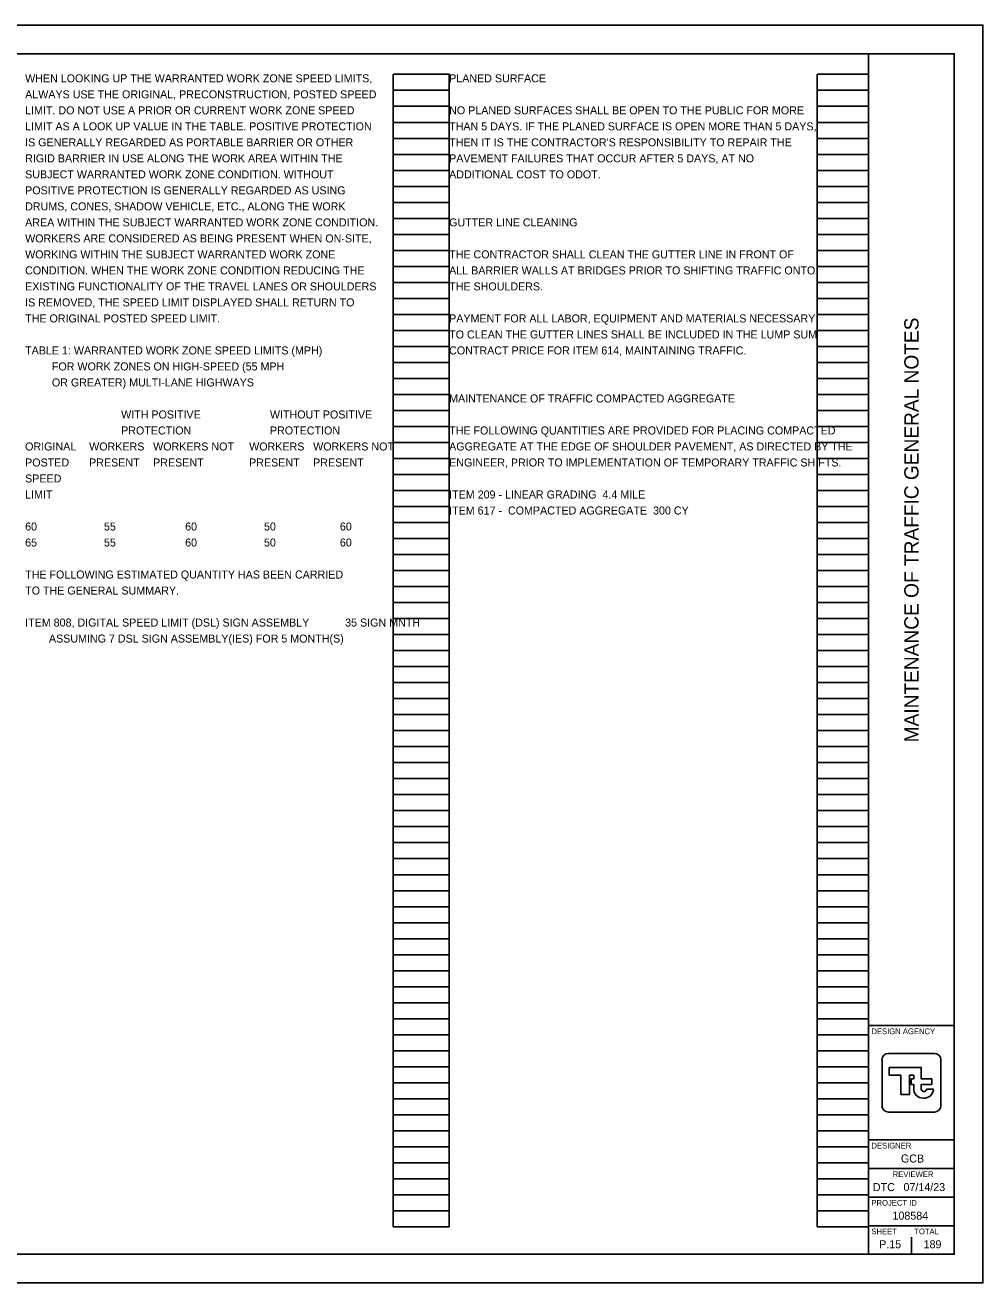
# Model space of a CAD drawing. Extents: x 0 to 34, y -3.9 to 22.
# Drawn here: x 17.24 to 34, y 0 to 22 of the extents above; entities that cross this region are included whole.
import ezdxf

# ---------------------------------------------------------------- set-up
doc = ezdxf.new("R2010")
doc.units = 0
for name, color, linetype in [('SH_Border', 7, 'Continuous'), ('SH_Cut_Line', 7, 'Continuous'), ('SH_Data', 7, 'Continuous'), ('SH_Text', 7, 'Continuous')]:
    doc.layers.add(name, color=color, linetype=linetype)

msp = doc.modelspace()

# ---------------------------------------------------------------- linework, layer by layer
at = {"layer": 'SH_Border'}
for p, q in [((32, 0.5), (32, 21.5)), ((32, 4.5), (33.5, 4.5)), ((32, 2.5), (33.5, 2.5)), ((32, 2), (33.5, 2)), ((32, 1.5), (33.5, 1.5)), ((32, 1), (33.5, 1))]:
    msp.add_line(p, q, dxfattribs=at)
msp.add_lwpolyline([(1.5, 21.5), (33.5, 21.5), (33.5, 0.5), (1.5, 0.5)], close=True, dxfattribs=at)
at = {"layer": 'SH_Cut_Line'}
msp.add_lwpolyline([(0, 0), (34, 0), (34, 22), (0, 22)], close=True, dxfattribs=at)
at = {"layer": 'SH_Data'}
for p, q in [((23.68, 0.98), (23.68, 21.14)), ((23.68, 21.14), (24.66, 21.14)), ((24.66, 0.98), (24.66, 21.14)), ((31.1, 0.98), (31.1, 21.14)), ((31.1, 21.14), (32, 21.14)), ((32, 0.98), (32, 21.14)), ((23.68, 20.86), (24.66, 20.86)), ((31.1, 20.86), (32, 20.86)), ((23.68, 20.58), (24.66, 20.58)), ((31.1, 20.58), (32, 20.58)), ((23.68, 20.3), (24.66, 20.3)), ((31.1, 20.3), (32, 20.3)), ((23.68, 20.02), (24.66, 20.02)), ((31.1, 20.02), (32, 20.02)), ((23.68, 19.74), (24.66, 19.74)), ((31.1, 19.74), (32, 19.74)), ((23.68, 19.46), (24.66, 19.46)), ((31.1, 19.46), (32, 19.46)), ((23.68, 19.18), (24.66, 19.18)), ((31.1, 19.18), (32, 19.18)), ((23.68, 18.9), (24.66, 18.9)), ((31.1, 18.9), (32, 18.9)), ((23.68, 18.62), (24.66, 18.62)), ((31.1, 18.62), (32, 18.62)), ((23.68, 18.34), (24.66, 18.34)), ((31.1, 18.34), (32, 18.34)), ((23.68, 18.06), (24.66, 18.06)), ((31.1, 18.06), (32, 18.06)), ((23.68, 17.78), (24.66, 17.78)), ((31.1, 17.78), (32, 17.78)), ((23.68, 17.5), (24.66, 17.5)), ((31.1, 17.5), (32, 17.5)), ((23.68, 17.22), (24.66, 17.22)), ((31.1, 17.22), (32, 17.22)), ((23.68, 16.94), (24.66, 16.94)), ((31.1, 16.94), (32, 16.94)), ((23.68, 16.66), (24.66, 16.66)), ((31.1, 16.66), (32, 16.66)), ((23.68, 16.38), (24.66, 16.38)), ((31.1, 16.38), (32, 16.38)), ((23.68, 16.1), (24.66, 16.1)), ((31.1, 16.1), (32, 16.1)), ((23.68, 15.82), (24.66, 15.82)), ((31.1, 15.82), (32, 15.82)), ((23.68, 15.54), (24.66, 15.54)), ((31.1, 15.54), (32, 15.54)), ((23.68, 15.26), (24.66, 15.26)), ((31.1, 15.26), (32, 15.26)), ((23.68, 14.98), (24.66, 14.98)), ((31.1, 14.98), (32, 14.98)), ((23.68, 14.7), (24.66, 14.7)), ((31.1, 14.7), (32, 14.7)), ((23.68, 14.42), (24.66, 14.42)), ((31.1, 14.42), (32, 14.42)), ((23.68, 14.14), (24.66, 14.14)), ((31.1, 14.14), (32, 14.14)), ((23.68, 13.86), (24.66, 13.86)), ((31.1, 13.86), (32, 13.86)), ((23.68, 13.58), (24.66, 13.58)), ((31.1, 13.58), (32, 13.58)), ((23.68, 13.3), (24.66, 13.3)), ((31.1, 13.3), (32, 13.3)), ((23.68, 13.02), (24.66, 13.02)), ((31.1, 13.02), (32, 13.02)), ((23.68, 12.74), (24.66, 12.74)), ((31.1, 12.74), (32, 12.74)), ((23.68, 12.46), (24.66, 12.46)), ((31.1, 12.46), (32, 12.46)), ((23.68, 12.18), (24.66, 12.18)), ((31.1, 12.18), (32, 12.18)), ((23.68, 11.9), (24.66, 11.9)), ((31.1, 11.9), (32, 11.9)), ((23.68, 11.62), (24.66, 11.62)), ((31.1, 11.62), (32, 11.62)), ((23.68, 11.34), (24.66, 11.34)), ((31.1, 11.34), (32, 11.34)), ((23.68, 11.06), (24.66, 11.06)), ((31.1, 11.06), (32, 11.06)), ((23.68, 10.78), (24.66, 10.78)), ((31.1, 10.78), (32, 10.78)), ((23.68, 10.5), (24.66, 10.5)), ((31.1, 10.5), (32, 10.5)), ((23.68, 10.22), (24.66, 10.22)), ((31.1, 10.22), (32, 10.22)), ((23.68, 9.94), (24.66, 9.94)), ((31.1, 9.94), (32, 9.94)), ((23.68, 9.66), (24.66, 9.66)), ((31.1, 9.66), (32, 9.66)), ((23.68, 9.38), (24.66, 9.38)), ((31.1, 9.38), (32, 9.38)), ((23.68, 9.1), (24.66, 9.1)), ((31.1, 9.1), (32, 9.1)), ((23.68, 8.82), (24.66, 8.82)), ((31.1, 8.82), (32, 8.82)), ((23.68, 8.54), (24.66, 8.54)), ((31.1, 8.54), (32, 8.54)), ((23.68, 8.26), (24.66, 8.26)), ((31.1, 8.26), (32, 8.26)), ((23.68, 7.98), (24.66, 7.98)), ((31.1, 7.98), (32, 7.98)), ((23.68, 7.7), (24.66, 7.7)), ((31.1, 7.7), (32, 7.7)), ((23.68, 7.42), (24.66, 7.42)), ((31.1, 7.42), (32, 7.42)), ((23.68, 7.14), (24.66, 7.14)), ((31.1, 7.14), (32, 7.14)), ((23.68, 6.86), (24.66, 6.86)), ((31.1, 6.86), (32, 6.86)), ((23.68, 6.58), (24.66, 6.58)), ((31.1, 6.58), (32, 6.58)), ((23.68, 6.3), (24.66, 6.3)), ((31.1, 6.3), (32, 6.3)), ((23.68, 6.02), (24.66, 6.02)), ((31.1, 6.02), (32, 6.02)), ((23.68, 5.74), (24.66, 5.74)), ((31.1, 5.74), (32, 5.74)), ((23.68, 5.46), (24.66, 5.46)), ((31.1, 5.46), (32, 5.46)), ((23.68, 5.18), (24.66, 5.18)), ((31.1, 5.18), (32, 5.18)), ((23.68, 4.9), (24.66, 4.9)), ((31.1, 4.9), (32, 4.9)), ((23.68, 4.62), (24.66, 4.62)), ((31.1, 4.62), (32, 4.62)), ((23.68, 4.34), (24.66, 4.34)), ((31.1, 4.34), (32, 4.34)), ((23.68, 4.06), (24.66, 4.06)), ((31.1, 4.06), (32, 4.06)), ((23.68, 3.78), (24.66, 3.78)), ((31.1, 3.78), (32, 3.78)), ((23.68, 3.5), (24.66, 3.5)), ((31.1, 3.5), (32, 3.5)), ((32.75, 3.5), (32.75, 3.5)), ((32.791, 3.415), (32.791, 3.415)), ((33.136, 3.385), (33.015, 3.385)), ((23.68, 3.22), (24.66, 3.22)), ((31.1, 3.22), (32, 3.22)), ((23.68, 2.94), (24.66, 2.94)), ((31.1, 2.94), (32, 2.94)), ((23.68, 2.66), (24.66, 2.66)), ((31.1, 2.66), (32, 2.66)), ((23.68, 2.38), (24.66, 2.38)), ((31.1, 2.38), (32, 2.38)), ((23.68, 2.1), (24.66, 2.1)), ((31.1, 2.1), (32, 2.1)), ((23.68, 1.82), (24.66, 1.82)), ((31.1, 1.82), (32, 1.82)), ((23.68, 1.54), (24.66, 1.54)), ((31.1, 1.54), (32, 1.54)), ((23.68, 1.26), (24.66, 1.26)), ((31.1, 1.26), (32, 1.26)), ((23.68, 0.98), (24.66, 0.98)), ((31.1, 0.98), (32, 0.98)), ((32.375, 0.675), (32.375, 0.675)), ((32.75, 0.5), (32.75, 0.8))]:
    msp.add_line(p, q, dxfattribs=at)
for points in [[(32.348, 4.014), (33.152, 4.014)], [(32.236, 3.099), (32.236, 3.901)], [(32.922, 3.399), (32.922, 3.47), (33.107, 3.47), (33.107, 3.568), (32.922, 3.568), (32.922, 3.768), (32.361, 3.768), (32.361, 3.632), (32.566, 3.632), (32.566, 3.294), (32.715, 3.294), (32.715, 3.63), (32.79, 3.63), (32.79, 3.568), (32.748, 3.568), (32.748, 3.47), (32.79, 3.47), (32.79, 3.415), (32.791, 3.415)], [(33.264, 3.901), (33.264, 3.099)], [(33.152, 2.986), (32.348, 2.986)]]:
    msp.add_lwpolyline(points, dxfattribs=at)
for centre, radius, start, end in [((32.348, 3.901), 0.113, 90, 180), ((33.152, 3.901), 0.113, 360, 90), ((32.949, 3.392), 0.16, 171.8856, 274.8323), ((32.968, 3.392), 0.0473, 171.8856, 350.9243), ((32.976, 3.392), 0.16, 265.1677, 357.3201), ((32.348, 3.099), 0.113, 180, 270), ((33.152, 3.099), 0.113, 270, 360)]:
    msp.add_arc(centre, radius, start, end, dxfattribs=at)

# ---------------------------------------------------------------- texts
msp.add_text('MAINTENANCE OF TRAFFIC GENERAL NOTES', height=0.25, rotation=90, dxfattribs=at).set_placement((32.875, 9.455))
for s, height, p in [('DESIGN AGENCY', 0.1, (32.05, 4.35)), ('DESIGNER', 0.1, (32.05, 2.35)), ('GCB', 0.14, (32.566, 2.105)), ('REVIEWER', 0.1, (32.422, 1.85)), ('DTC', 0.14, (32.076, 1.605)), ('07/14/23', 0.14, (32.611, 1.605)), ('PROJECT ID', 0.1, (32.05, 1.35)), ('108584', 0.14, (32.418, 1.105)), ('SHEET', 0.1, (32.05, 0.85)), ('TOTAL', 0.1, (32.8, 0.85)), ('P.15', 0.14, (32.185, 0.605)), ('189', 0.14, (32.963, 0.605))]:
    msp.add_text(s, height=height, dxfattribs=at).set_placement(p)
at = {"layer": 'SH_Text'}
for s, p in [('WHEN LOOKING UP THE WARRANTED WORK ZONE SPEED LIMITS,', (17.24, 21)), ('PLANED SURFACE', (24.66, 21)), ('ALWAYS USE THE ORIGINAL, PRECONSTRUCTION, POSTED SPEED', (17.24, 20.72)), ('LIMIT. DO NOT USE A PRIOR OR CURRENT WORK ZONE SPEED', (17.24, 20.44)), ('NO PLANED SURFACES SHALL BE OPEN TO THE PUBLIC FOR MORE', (24.66, 20.44)), ('LIMIT AS A LOOK UP VALUE IN THE TABLE. POSITIVE PROTECTION', (17.24, 20.16)), ('THAN 5 DAYS. IF THE PLANED SURFACE IS OPEN MORE THAN 5 DAYS,', (24.66, 20.16)), ('IS GENERALLY REGARDED AS PORTABLE BARRIER OR OTHER', (17.24, 19.88)), ("THEN IT IS THE CONTRACTOR'S RESPONSIBILITY TO REPAIR THE", (24.66, 19.88)), ('RIGID BARRIER IN USE ALONG THE WORK AREA WITHIN THE', (17.24, 19.6)), ('PAVEMENT FAILURES THAT OCCUR AFTER 5 DAYS, AT NO', (24.66, 19.6)), ('SUBJECT WARRANTED WORK ZONE CONDITION. WITHOUT', (17.24, 19.32)), ('ADDITIONAL COST TO ODOT.', (24.66, 19.32)), ('POSITIVE PROTECTION IS GENERALLY REGARDED AS USING', (17.24, 19.04)), ('DRUMS, CONES, SHADOW VEHICLE, ETC., ALONG THE WORK', (17.24, 18.76)), ('AREA WITHIN THE SUBJECT WARRANTED WORK ZONE CONDITION.', (17.24, 18.48)), ('GUTTER LINE CLEANING', (24.66, 18.48)), ('WORKERS ARE CONSIDERED AS BEING PRESENT WHEN ON-SITE,', (17.24, 18.2)), ('WORKING WITHIN THE SUBJECT WARRANTED WORK ZONE', (17.24, 17.92)), ('THE CONTRACTOR SHALL CLEAN THE GUTTER LINE IN FRONT OF', (24.66, 17.92)), ('CONDITION. WHEN THE WORK ZONE CONDITION REDUCING THE', (17.24, 17.64)), ('ALL BARRIER WALLS AT BRIDGES PRIOR TO SHIFTING TRAFFIC ONTO', (24.66, 17.64)), ('EXISTING FUNCTIONALITY OF THE TRAVEL LANES OR SHOULDERS', (17.24, 17.36)), ('THE SHOULDERS.', (24.66, 17.36)), ('IS REMOVED, THE SPEED LIMIT DISPLAYED SHALL RETURN TO', (17.24, 17.08)), ('THE ORIGINAL POSTED SPEED LIMIT.', (17.24, 16.8)), ('PAYMENT FOR ALL LABOR, EQUIPMENT AND MATERIALS NECESSARY', (24.66, 16.8)), ('TO CLEAN THE GUTTER LINES SHALL BE INCLUDED IN THE LUMP SUM', (24.66, 16.52)), ('TABLE 1: WARRANTED WORK ZONE SPEED LIMITS (MPH)', (17.24, 16.24)), ('CONTRACT PRICE FOR ITEM 614, MAINTAINING TRAFFIC.', (24.66, 16.24)), ('         FOR WORK ZONES ON HIGH-SPEED (55 MPH', (17.24, 15.96)), ('         OR GREATER) MULTI-LANE HIGHWAYS', (17.24, 15.68)), ('MAINTENANCE OF TRAFFIC COMPACTED AGGREGATE', (24.66, 15.4)), ('WITH POSITIVE    ', (18.92, 15.12)), ('       WITHOUT POSITIVE', (21.16, 15.12)), ('PROTECTION', (18.92, 14.84)), ('       PROTECTION', (21.16, 14.84)), ('THE FOLLOWING QUANTITIES ARE PROVIDED FOR PLACING COMPACTED ', (24.66, 14.84)), ('ORIGINAL', (17.24, 14.56)), ('WORKERS', (18.36, 14.56)), ('WORKERS NOT', (19.48, 14.56)), ('WORKERS', (21.16, 14.56)), ('WORKERS NOT', (22.28, 14.56)), ('AGGREGATE AT THE EDGE OF SHOULDER PAVEMENT, AS DIRECTED BY THE ', (24.66, 14.56)), ('POSTED', (17.24, 14.28)), ('PRESENT', (18.36, 14.28)), ('PRESENT', (19.48, 14.28)), ('PRESENT', (21.16, 14.28)), ('PRESENT', (22.28, 14.28)), ('ENGINEER, PRIOR TO IMPLEMENTATION OF TEMPORARY TRAFFIC SHIFTS.', (24.66, 14.28)), ('SPEED', (17.24, 14)), ('ITEM 209 - LINEAR GRADING  4.4 MILE', (24.66, 13.72)), ('LIMIT', (17.24, 13.72)), ('ITEM 617 -  COMPACTED AGGREGATE  300 CY', (24.66, 13.44)), ('60', (17.24, 13.16)), ('     55', (18.36, 13.16)), ('60', (20.04, 13.16)), ('     50', (21.16, 13.16)), ('         60', (22.28, 13.16)), ('65', (17.24, 12.88)), ('     55', (18.36, 12.88)), ('60', (20.04, 12.88)), ('     50', (21.16, 12.88)), ('         60', (22.28, 12.88)), ('THE FOLLOWING ESTIMATED QUANTITY HAS BEEN CARRIED', (17.24, 12.32)), ('TO THE GENERAL SUMMARY.', (17.24, 12.04)), ('ITEM 808, DIGITAL SPEED LIMIT (DSL) SIGN ASSEMBLY', (17.24, 11.48)), ('35 SIGN MNTH', (22.84, 11.48)), ('        ASSUMING 7 DSL SIGN ASSEMBLY(IES) FOR 5 MONTH(S)', (17.24, 11.2))]:
    msp.add_text(s, height=0.14, dxfattribs=at).set_placement(p)

doc.saveas('drawing.dxf')
